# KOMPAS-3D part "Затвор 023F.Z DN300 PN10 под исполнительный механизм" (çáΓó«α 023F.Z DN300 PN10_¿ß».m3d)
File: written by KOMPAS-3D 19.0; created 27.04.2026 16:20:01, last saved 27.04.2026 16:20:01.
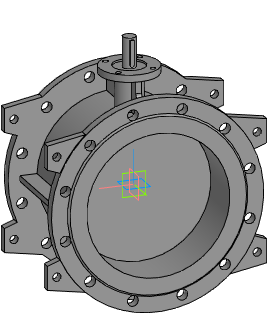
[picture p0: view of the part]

Document properties: Автор: Евгений; Полное имя файла: Z:\3.Личные\kachalov\3d для проектировщиков\1.7 Тип 023F.Z Затвор дисковый поворотный фланцевый с двумя эксцентриками\Затвор 023F.Z DN200-DN1600_исп\_stp_Затвор 023F.Z DN200-DN1600_исп\Затвор 023F.Z DN300 PN10_исп.m3d

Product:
- Part/product: Затвор 023F.Z DN300 PN10 под исполнительный механизм

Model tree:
1. Операция без истории:1  (labels: Затвор 023F.Z DN300 PN10 под исполнительный механизм)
